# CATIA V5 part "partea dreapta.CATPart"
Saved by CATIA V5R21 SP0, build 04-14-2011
Part number: 2. 6 DOF ARM ASSEMBLY_sldprt_AllCATPart
Bounding box of the stored display mesh (mm): x 83.286 to 178.079, y 285.006 to 296.925, z 109.951 to 144.512
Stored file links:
  C:\Users\laurc\OneDrive\Desktop\Practica de cercetare\simulare prehensor\partea dreapta.CATPart
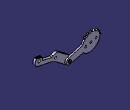
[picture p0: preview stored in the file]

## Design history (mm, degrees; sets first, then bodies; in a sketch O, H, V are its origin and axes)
Body1 (main body)
Body2 "2. 6 DOF ARM ASSEMBLY_sldprt.1"
  Solid1: solid without history
  Body3 "2. 6 DOF ARM ASSEMBLY_sldprt.1\\4. gear link smal hole-2-solid1"
    Solid2 "Solid.1": solid without history
  Add1 "2. 6 DOF ARM ASSEMBLY_sldprt.1\\4. gear link smal hole-2-solid1": tool Body3
  Body4 "2. 6 DOF ARM ASSEMBLY_sldprt.1\\pan cross head_am-69-solid1"
    Solid3 "Solid.1": solid without history
  Add2 "2. 6 DOF ARM ASSEMBLY_sldprt.1\\pan cross head_am-69-solid1": tool Body4
  Body5 "2. 6 DOF ARM ASSEMBLY_sldprt.1\\hex nut style 1_am-45-solid1"
    Solid4 "Solid.1": solid without history
  Add3 "2. 6 DOF ARM ASSEMBLY_sldprt.1\\hex nut style 1_am-45-solid1": tool Body5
